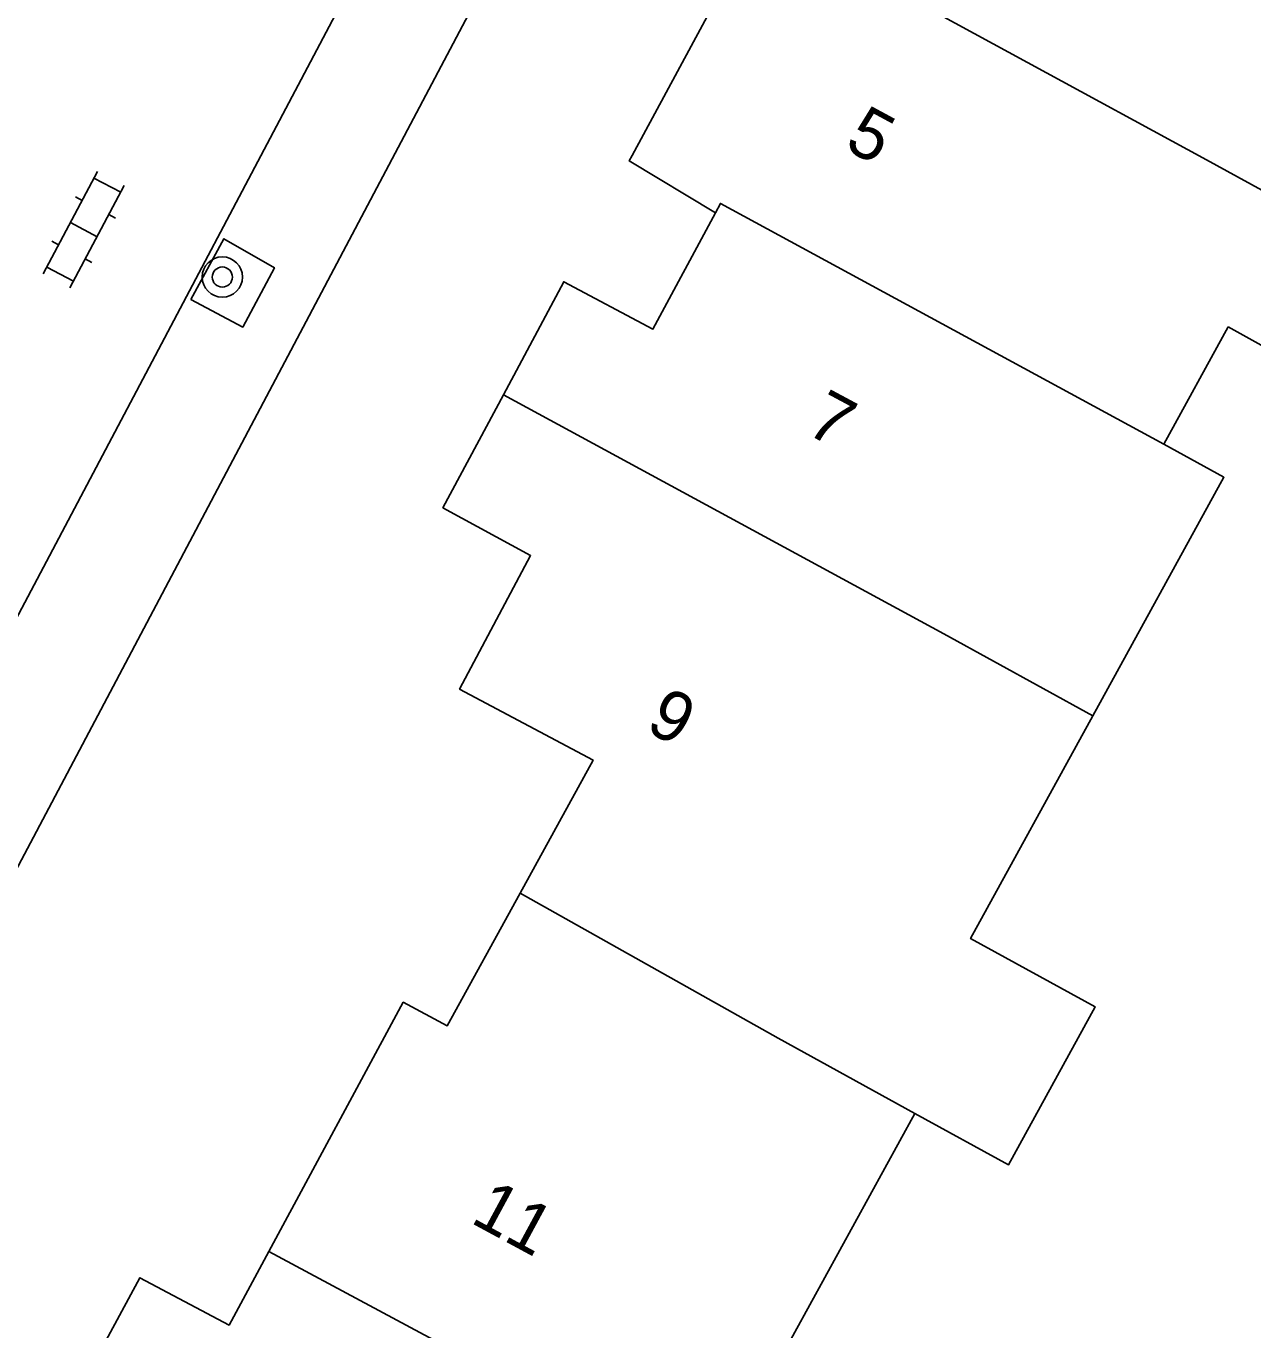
# Model space of a CAD drawing. Extents: x 136000 to 141000, y 400494 to 402006.
# Drawn here: x 137817.15 to 137841.52, y 401652.43 to 401678.33 of the extents above; entities that cross this region are included whole.
import ezdxf

# ---------------------------------------------------------------- set-up
doc = ezdxf.new("R2010")
doc.units = 0
for name, color, linetype in [('gg-anno-huisnummerreeks BGT', 7, 'Continuous'), ('gg-bbg-gedigitaliseerde bebouwing', 7, 'Continuous'), ('gg-bbg-hoofdgebouw', 7, 'Continuous'), ('gg-bbg-tussenscheiding', 7, 'Continuous'), ('gg-knt-verharding', 7, 'Continuous'), ('gg-knt-verharding nz', 7, 'Continuous'), ('gt-symb-boom', 7, 'Continuous'), ('gt-symb-klinker verharding', 7, 'Continuous')]:
    doc.layers.add(name, color=color, linetype=linetype)

# ---------------------------------------------------------------- blocks, each defined once
blk = doc.blocks.new('gt0-BOOM')
at = {"layer": 'gt-symb-boom'}
for radius in [0.4, 0.2]:
    blk.add_circle((0, 0), radius, dxfattribs=at)
blk = doc.blocks.new('gt0-KL1')
at = {"layer": 'gt-symb-klinker verharding'}
for p, q in [((-1.15, 0.3), (1.15, 0.3)), ((-1, -0.3), (-1, 0.3)), ((-0.5, 0.3), (-0.5, 0.45)), ((0, -0.3), (0, 0.3)), ((0.5, 0.3), (0.5, 0.45)), ((1, -0.3), (1, 0.3)), ((-1.15, -0.3), (1.15, -0.3)), ((-0.5, -0.45), (-0.5, -0.3)), ((0.5, -0.45), (0.5, -0.3))]:
    blk.add_line(p, q, dxfattribs=at)

msp = doc.modelspace()

# ---------------------------------------------------------------- linework, layer by layer
at = {"layer": 'gg-bbg-gedigitaliseerde bebouwing'}
for p, q in [((137839.747, 401670.023), (137841.025, 401672.351)), ((137831.958, 401651.553), (137834.804, 401656.734))]:
    msp.add_line(p, q, dxfattribs=at)
for points in [[(137843.52, 401674.064), (137842.219, 401671.695), (137841.025, 401672.351)], [(137838.338, 401664.63), (137840.94, 401669.367), (137839.747, 401670.023)], [(137838.338, 401664.63), (137835.91, 401660.207), (137838.386, 401658.847), (137836.664, 401655.713), (137834.804, 401656.734)]]:
    msp.add_lwpolyline(points, dxfattribs=at)
at = {"layer": 'gg-bbg-hoofdgebouw'}
for points in [[(137829.186, 401675.756), (137831.036, 401679.183), (137832.003, 401678.664), (137832.71, 401679.964)], [(137830.84, 401674.618), (137829.128, 401675.648), (137829.186, 401675.756)], [(137830.84, 401674.618), (137829.6, 401672.31), (137827.83, 401673.25), (137826.63, 401671.005)], [(137826.63, 401671.005), (137825.43, 401668.76), (137827.17, 401667.81), (137825.76, 401665.16), (137828.41, 401663.75), (137826.96, 401661.11)], [(137826.96, 401661.11), (137825.51, 401658.47), (137824.64, 401658.94), (137821.969, 401653.992)], [(137821.969, 401653.992), (137821.18, 401652.53), (137819.41, 401653.47), (137817.612, 401650.147)]]:
    msp.add_lwpolyline(points, dxfattribs=at)
at = {"layer": 'gg-bbg-tussenscheiding'}
for p, q in [((137840.594, 401675.671), (137843.52, 401674.064)), ((137826.63, 401671.005), (137835.38, 401666.255)), ((137835.38, 401666.255), (137838.338, 401664.63)), ((137826.96, 401661.11), (137832.088, 401658.226)), ((137832.088, 401658.226), (137834.804, 401656.734)), ((137821.969, 401653.992), (137830.721, 401649.302))]:
    msp.add_line(p, q, dxfattribs=at)
for points in [[(137833.562, 401679.686), (137833.485, 401679.542), (137840.594, 401675.671)], [(137830.84, 401674.618), (137830.94, 401674.804), (137839.747, 401670.023)]]:
    msp.add_lwpolyline(points, dxfattribs=at)
at = {"layer": 'gg-knt-verharding'}
msp.add_line((137832.057, 401690.136), (137813.166, 401654.412), dxfattribs=at)
msp.add_lwpolyline([(137820.42, 401672.899), (137821.452, 401672.349), (137822.081, 401673.529), (137821.08, 401674.104), (137820.42, 401672.899)], dxfattribs=at)
at = {"layer": 'gg-knt-verharding nz'}
msp.add_line((137811.121, 401655.529), (137830.641, 401692.463), dxfattribs=at)

# ---------------------------------------------------------------- block references
at = {"layer": 'gt-symb-boom'}
msp.add_blockref('gt0-BOOM', (137821.047, 401673.343), dxfattribs=at)
at = {"layer": 'gt-symb-klinker verharding', "rotation": 62.02527007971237}
msp.add_blockref('gt0-KL1', (137818.294, 401674.284), dxfattribs=at)

# ---------------------------------------------------------------- texts
at = {"layer": 'gg-anno-huisnummerreeks BGT'}
for s, rotation, p in [('5', 331.6, (137833.372, 401675.907)), ('7', 331.8, (137832.599, 401670.261)), ('9', 332, (137829.42, 401664.351)), ('11', 331.6, (137825.949, 401654.578))]:
    msp.add_text(s, height=1, rotation=rotation, dxfattribs=at).set_placement(p)

doc.saveas('drawing.dxf')
